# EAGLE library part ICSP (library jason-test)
Microchip ICSP header
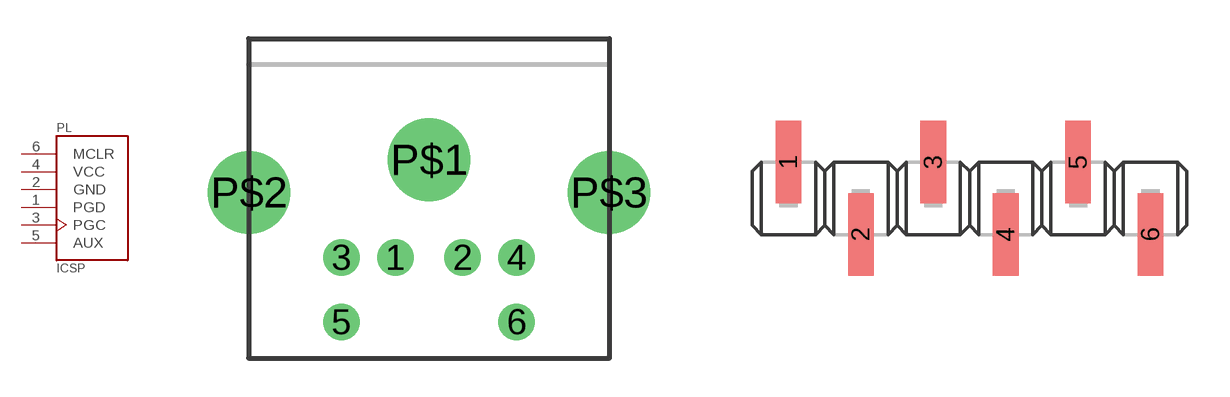
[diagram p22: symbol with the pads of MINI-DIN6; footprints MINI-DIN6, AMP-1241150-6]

Designator prefix PL

## ICSPDIN  [MINI-DIN6]
1  PGD
2  GND  pwr
3  PGC  out
4  VCC  pwr
5  AUX  out
6  MCLR  out

## ICSPSMT  [AMP-1241150-6]
1  MCLR  out
2  VCC  pwr
3  GND  pwr
4  PGD
5  PGC  out
6  AUX  out

## ICSP  [6X1-ICSP]
PIN1  MCLR  out
PIN2  VCC  pwr
PIN3  GND  pwr
PIN4  PGD
PIN5  PGC  out
PIN6  AUX  out

## Footprint MINI-DIN6 (pad centres in mm)
drill 0.9 round: 1 -1.3,-8.5; 2 1.3,-8.5; 3 -3.4,-8.5; 4 3.4,-8.5; 5 -3.4,-11; 6 3.4,-11
drill 2.2 round: P$1 0,-4.7; P$2 -6.985,-5.97; P$3 6.985,-5.97

## Footprint AMP-1241150-6 (pad centres in mm)
AMPMODU II 2.54mm SMT unshrouded 6-position
smd 0.9 x 2.9: 1 -6.35,1.27; 2 -3.81,-1.27; 3 -1.27,1.27; 4 1.27,-1.27; 5 3.81,1.27; 6 6.35,-1.27

## Footprint 6X1-ICSP (pad centres in mm)
drill 0.8 pad 1.676 octagon: PIN1 -6.35,0
drill 0.8 pad 1.676 round: PIN2 -3.81,0; PIN3 -1.27,0; PIN4 1.27,0; PIN5 3.81,0; PIN6 6.35,0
